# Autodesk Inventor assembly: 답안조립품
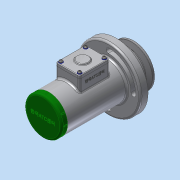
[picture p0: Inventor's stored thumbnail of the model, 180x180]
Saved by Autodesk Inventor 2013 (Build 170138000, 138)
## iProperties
Created: 2017-05
Part Number: 답안조립품
Document SubType Name: Assembly
Designer: dgall
Author: dgall
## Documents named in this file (20)
- C:\Users\dgall\Desktop\470507V1017\답안조립품.iam
- C:\Users\dgall\Desktop\470507V1017\본체.ipt
- C:\Users\dgall\Desktop\470507V1017\V-벨트풀리.ipt
- C:\Users\dgall\Desktop\470507V1017\너트 M10.ipt
- C:\Users\dgall\Desktop\470507V1017\멈춤링 15 x 1.ipt
- C:\Users\dgall\Desktop\470507V1017\멈춤링 35x1.6.ipt
- C:\Users\dgall\Desktop\470507V1017\베어링 15 x 35 x 11.ipt
- C:\Users\dgall\Desktop\470507V1017\볼트 M4 x 10.ipt
- C:\Users\dgall\Desktop\470507V1017\부시1.ipt
- C:\Users\dgall\Desktop\470507V1017\부시2.ipt
- C:\Users\dgall\Desktop\470507V1017\사이드 커버.ipt
- 사이드 커버.ipt
- C:\Users\dgall\Desktop\470507V1017\십자볼트 M3 x 10.ipt
- C:\Users\dgall\Desktop\470507V1017\오일 실 15 25 7.ipt
- C:\Users\dgall\Desktop\470507V1017\와셔 3x6.ipt
- C:\Users\dgall\Desktop\470507V1017\와셔 4x16.ipt
- C:\Users\dgall\Desktop\470507V1017\와셔 10x21.ipt
- C:\Users\dgall\Desktop\470507V1017\축.ipt
- C:\Users\dgall\Desktop\470507V1017\키 4 x 4 x 18.ipt
- C:\Users\dgall\Desktop\470507V1017\탑 커버.ipt
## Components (2 placed, 2 different names)
1. V-벨트풀리:1 — 각도:2
2. ISO 4017 M4 x 10:1
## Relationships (1: Angle 1)
- 각도:2 [Angle]: V-벨트풀리:1
